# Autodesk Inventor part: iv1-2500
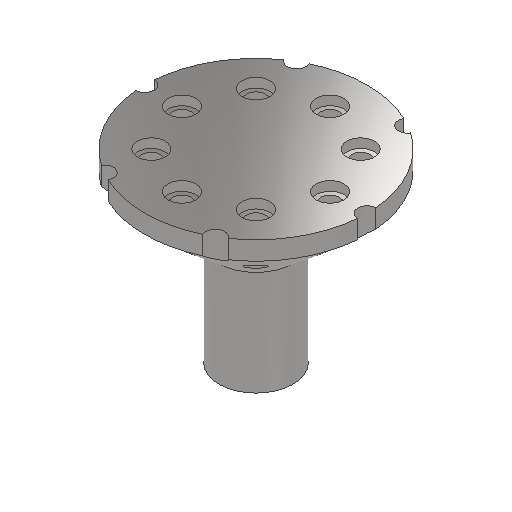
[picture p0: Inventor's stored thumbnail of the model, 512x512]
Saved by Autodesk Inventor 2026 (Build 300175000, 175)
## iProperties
Created: 2004-09
Part Number: iv1-2500
Document SubType Name: Modeling
Designer: Lars Bertram Pedersen
Manufacturer: Standard
Standards Organization: Custom
Material: Steel, Mild
Density: 7.85 g/cm^3
Appearance: Semi-Polished
Mass: 2694.68 g
Surface Area: 424.568 cm^2
Volume: 343.272 cm^3
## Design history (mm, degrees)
revolve "Revolution1" stored, may be unused: angle "d5" = 90 deg
sketch "Sketch2"
  geometry: C1 r 5 at (0, 60); 1 further point
  constraints: 1 centre point, 1 vertical alignment, 1 other
  dimensions: "d7" = 10 diameter of C1
extrude "Extrusion1" cut sketch "Sketch2" extent not by distance; stored distance "d8" = 10; taper "d9" = 0 deg
pattern_circular "Circular Pattern1" dims angle "d12" = 360 deg
sketch "Sketch3"
  geometry: L1 (0, 29.696)-(0, -144.949) reference; A1 r 60 centre (0, -60) between (-4.996, -0.208) and (-49.283, -25.778) reference; 1 further point
  dimensions: "d21" = 40 distance of point (0, -20) A1.centre
hole "Hole2" sketch "Sketch3" diameter "d22" = 10; stored, may be unused: countersink angle "d26" = 90 deg, drill point angle "d28" = 118 deg; dims "d23" = 6, "d24" = 15, "d25" = 5, "d27" = 20
pattern_circular "Circular Pattern2" dims angle "d31" = 360 deg
body "Solid1"
sketch "Sketch1"
  geometry: L1 (0, 100)-(60, 100); L2 (60, 100)-(60, 90); L3 (60, 90)-(20, 56.436); L4 (20, 56.436)-(20, 0); L5 (20, 0)-(0, 0); L6 (0, 0)-(0, 100); 1 further point
  constraints: 12 end point, 3 parallel, 1 coincident, 1 horizontal, 1 perpendicular
  dimensions: "d0" = 10 distance of L1.end L2.end; "d1" = 60 distance of L1.start L1.end; "d2" = 20 distance of L4.end L5.end; "d4" = 100 distance of L5.end L1.start; "d32" = 50 deg angle of L3 L2
